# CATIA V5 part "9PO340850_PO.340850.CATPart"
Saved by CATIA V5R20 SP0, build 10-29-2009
Part number: 9PO340850_PO.340850
Revision: ANY
Definition: UNKNOWN
Nomenclature: 9PO340850_PO.340850
Source: Unknown
Bounding box of the stored display mesh (mm): x -8 to 8, y 0 to 33.4, z -8 to 8
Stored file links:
  C:\Users\Utente\Desktop\IO LAVORO\3D X SITO CF\CUMSA\3D files PO\PO 340850\9PO340850_PO.340850.CATPart
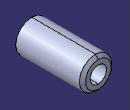
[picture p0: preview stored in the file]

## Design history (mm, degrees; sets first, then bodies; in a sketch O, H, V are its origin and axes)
Body1 "Chaflán2" (main body)
  Solid1: solid without history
